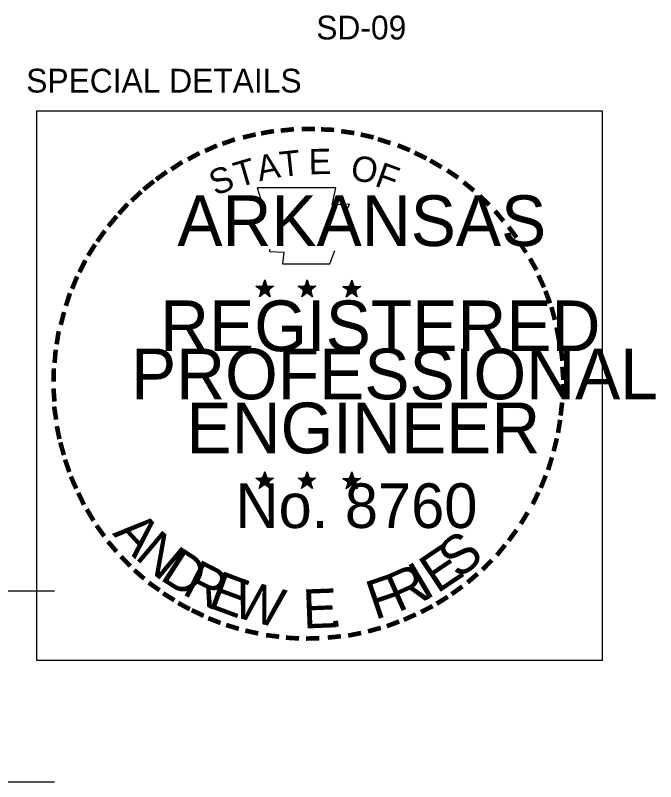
# Model space of a CAD drawing. Extents: x 1227242 to 1227801, y 152460 to 152569.
# Drawn here: x 1227371.723 to 1227374.884, y 152475.874 to 152479.655 of the extents above; entities that cross this region are included whole.
import ezdxf

# ---------------------------------------------------------------- set-up
doc = ezdxf.new("R2010")
doc.units = 0
for name, color, linetype in [('Default', 7, 'Continuous'), ('R_Border', 7, 'Continuous'), ('R_Border PE', 7, 'Continuous'), ('R_Border Prem', 7, 'Continuous')]:
    doc.layers.add(name, color=color, linetype=linetype)

msp = doc.modelspace()

# ---------------------------------------------------------------- linework, layer by layer
at = {"layer": 'Default'}
for p, q in [((1227362.7076, 152476.8155), (1227371.9168, 152476.8155)), ((1227362.7076, 152475.8742), (1227371.9168, 152475.8742))]:
    msp.add_line(p, q, dxfattribs=at)
at = {"layer": 'R_Border PE'}
for p, q in [((1227372.9545, 152478.3508), (1227372.9482, 152478.3196)), ((1227372.9545, 152478.3508), (1227372.9495, 152478.3183)), ((1227372.9545, 152478.3508), (1227372.9532, 152478.3196)), ((1227372.9545, 152478.3046), (1227372.9545, 152478.3508)), ((1227372.9545, 152478.3508), (1227372.9632, 152478.3183)), ((1227372.9545, 152478.3508), (1227372.9607, 152478.3196)), ((1227372.9545, 152478.3508), (1227372.9582, 152478.3196)), ((1227373.1632, 152478.3508), (1227373.157, 152478.3196)), ((1227373.1632, 152478.3508), (1227373.1582, 152478.3183)), ((1227373.1632, 152478.3508), (1227373.1607, 152478.3196)), ((1227373.1632, 152478.3046), (1227373.1632, 152478.3508)), ((1227373.1632, 152478.3508), (1227373.172, 152478.3183)), ((1227373.1632, 152478.3508), (1227373.1695, 152478.3196)), ((1227373.1632, 152478.3508), (1227373.1657, 152478.3196)), ((1227373.3845, 152478.3483), (1227373.377, 152478.3183)), ((1227373.3845, 152478.3483), (1227373.3795, 152478.3171)), ((1227373.3845, 152478.3483), (1227373.382, 152478.3171)), ((1227373.3845, 152478.3033), (1227373.3845, 152478.3483)), ((1227373.3845, 152478.3483), (1227373.3932, 152478.3171)), ((1227373.3845, 152478.3483), (1227373.3907, 152478.3171)), ((1227373.3845, 152478.3483), (1227373.387, 152478.3183)), ((1227372.9107, 152478.3183), (1227372.9545, 152478.3046)), ((1227372.9107, 152478.3183), (1227372.9432, 152478.3158)), ((1227372.9107, 152478.3183), (1227372.9432, 152478.3133)), ((1227372.9107, 152478.3183), (1227372.942, 152478.3108)), ((1227372.9107, 152478.3183), (1227372.942, 152478.3058)), ((1227372.9107, 152478.3183), (1227372.9407, 152478.3033)), ((1227372.9107, 152478.3183), (1227372.9407, 152478.3008)), ((1227372.9982, 152478.3183), (1227372.9545, 152478.3046)), ((1227372.9982, 152478.3183), (1227372.9595, 152478.3158)), ((1227372.9982, 152478.3183), (1227372.962, 152478.3121)), ((1227372.9982, 152478.3183), (1227372.962, 152478.3096)), ((1227372.9982, 152478.3183), (1227372.9707, 152478.3071)), ((1227372.9982, 152478.3183), (1227372.9732, 152478.3058)), ((1227372.9982, 152478.3183), (1227372.9745, 152478.3046)), ((1227373.1195, 152478.3183), (1227373.1632, 152478.3046)), ((1227373.1195, 152478.3183), (1227373.152, 152478.3158)), ((1227373.1195, 152478.3183), (1227373.152, 152478.3133)), ((1227373.1195, 152478.3183), (1227373.1507, 152478.3108)), ((1227373.1195, 152478.3183), (1227373.1495, 152478.3058)), ((1227373.1195, 152478.3183), (1227373.1495, 152478.3033)), ((1227373.1195, 152478.3183), (1227373.1495, 152478.3008)), ((1227373.207, 152478.3183), (1227373.1632, 152478.3046)), ((1227373.207, 152478.3183), (1227373.1682, 152478.3158)), ((1227373.207, 152478.3183), (1227373.1707, 152478.3121)), ((1227373.207, 152478.3183), (1227373.1707, 152478.3096)), ((1227373.207, 152478.3183), (1227373.1795, 152478.3071)), ((1227373.207, 152478.3183), (1227373.182, 152478.3058)), ((1227373.207, 152478.3183), (1227373.1832, 152478.3046)), ((1227373.3407, 152478.3171), (1227373.3845, 152478.3033)), ((1227373.3407, 152478.3171), (1227373.3732, 152478.3133)), ((1227373.3407, 152478.3171), (1227373.372, 152478.3108)), ((1227373.3407, 152478.3171), (1227373.372, 152478.3096)), ((1227373.3407, 152478.3171), (1227373.3707, 152478.3046)), ((1227373.3407, 152478.3171), (1227373.3707, 152478.3021)), ((1227373.3407, 152478.3171), (1227373.3707, 152478.2996)), ((1227373.4282, 152478.3171), (1227373.3845, 152478.3033)), ((1227373.4282, 152478.3171), (1227373.3895, 152478.3146)), ((1227373.4282, 152478.3171), (1227373.392, 152478.3108)), ((1227373.4282, 152478.3171), (1227373.392, 152478.3083)), ((1227373.4282, 152478.3171), (1227373.4007, 152478.3058)), ((1227373.4282, 152478.3171), (1227373.402, 152478.3046)), ((1227373.4282, 152478.3171), (1227373.4045, 152478.3033)), ((1227372.9282, 152478.2671), (1227372.9545, 152478.3046)), ((1227372.9282, 152478.2671), (1227372.942, 152478.3021)), ((1227372.9282, 152478.2671), (1227372.9432, 152478.2983)), ((1227372.9282, 152478.2671), (1227372.9457, 152478.2971)), ((1227372.9282, 152478.2671), (1227372.9545, 152478.2946)), ((1227372.9282, 152478.2671), (1227372.9495, 152478.2933)), ((1227372.9282, 152478.2671), (1227372.9557, 152478.2908)), ((1227372.982, 152478.2671), (1227372.9545, 152478.3046)), ((1227372.982, 152478.2671), (1227372.9545, 152478.2946)), ((1227372.982, 152478.2671), (1227372.9545, 152478.2908)), ((1227372.982, 152478.2671), (1227372.9595, 152478.2933)), ((1227372.982, 152478.2671), (1227372.9632, 152478.2983)), ((1227372.982, 152478.2671), (1227372.9645, 152478.3033)), ((1227372.982, 152478.2671), (1227372.967, 152478.3046)), ((1227373.137, 152478.2671), (1227373.1632, 152478.3046)), ((1227373.137, 152478.2671), (1227373.1507, 152478.3021)), ((1227373.137, 152478.2671), (1227373.152, 152478.2983)), ((1227373.137, 152478.2671), (1227373.1545, 152478.2971)), ((1227373.137, 152478.2671), (1227373.1632, 152478.2946)), ((1227373.137, 152478.2671), (1227373.1582, 152478.2933)), ((1227373.137, 152478.2671), (1227373.1645, 152478.2908)), ((1227373.1907, 152478.2671), (1227373.1632, 152478.3046)), ((1227373.1907, 152478.2671), (1227373.1632, 152478.2946)), ((1227373.1907, 152478.2671), (1227373.1632, 152478.2908)), ((1227373.1907, 152478.2671), (1227373.1682, 152478.2933)), ((1227373.1907, 152478.2671), (1227373.172, 152478.2983)), ((1227373.1907, 152478.2671), (1227373.1732, 152478.3033)), ((1227373.1907, 152478.2671), (1227373.1757, 152478.3046)), ((1227373.357, 152478.2658), (1227373.3845, 152478.3033)), ((1227373.357, 152478.2658), (1227373.372, 152478.3008)), ((1227373.357, 152478.2658), (1227373.3732, 152478.2971)), ((1227373.357, 152478.2658), (1227373.3757, 152478.2958)), ((1227373.357, 152478.2658), (1227373.3845, 152478.2933)), ((1227373.357, 152478.2658), (1227373.3795, 152478.2921)), ((1227373.357, 152478.2658), (1227373.3857, 152478.2896)), ((1227373.4107, 152478.2658), (1227373.3845, 152478.3033)), ((1227373.4107, 152478.2658), (1227373.3845, 152478.2933)), ((1227373.4107, 152478.2658), (1227373.3845, 152478.2896)), ((1227373.4107, 152478.2658), (1227373.3895, 152478.2921)), ((1227373.4107, 152478.2658), (1227373.3932, 152478.2971)), ((1227373.4107, 152478.2658), (1227373.3945, 152478.3021)), ((1227373.4107, 152478.2658), (1227373.397, 152478.3021)), ((1227372.9545, 152477.4033), (1227372.947, 152477.3733)), ((1227372.9545, 152477.4033), (1227372.9495, 152477.3721)), ((1227372.9545, 152477.4033), (1227372.952, 152477.3721)), ((1227372.9545, 152477.3583), (1227372.9545, 152477.4033)), ((1227372.9545, 152477.4033), (1227372.9632, 152477.3721)), ((1227372.9545, 152477.4033), (1227372.9607, 152477.3721)), ((1227372.9545, 152477.4033), (1227372.957, 152477.3721)), ((1227373.1632, 152477.4033), (1227373.1557, 152477.3733)), ((1227373.1632, 152477.4033), (1227373.1582, 152477.3721)), ((1227373.1632, 152477.4033), (1227373.1607, 152477.3721)), ((1227373.1632, 152477.3583), (1227373.1632, 152477.4033)), ((1227373.1632, 152477.4033), (1227373.1707, 152477.3721)), ((1227373.1632, 152477.4033), (1227373.1695, 152477.3721)), ((1227373.1632, 152477.4033), (1227373.1657, 152477.3721)), ((1227373.3845, 152477.4021), (1227373.377, 152477.3708)), ((1227373.3845, 152477.4021), (1227373.3795, 152477.3708)), ((1227373.3845, 152477.4021), (1227373.382, 152477.3708)), ((1227373.3845, 152477.3571), (1227373.3845, 152477.4021)), ((1227373.3845, 152477.4021), (1227373.392, 152477.3708)), ((1227373.3845, 152477.4021), (1227373.3907, 152477.3708)), ((1227373.3845, 152477.4021), (1227373.387, 152477.3708)), ((1227372.9107, 152477.3721), (1227372.9545, 152477.3583)), ((1227372.9107, 152477.3721), (1227372.9432, 152477.3683)), ((1227372.9107, 152477.3721), (1227372.942, 152477.3658)), ((1227372.9107, 152477.3721), (1227372.942, 152477.3646)), ((1227372.9107, 152477.3721), (1227372.9407, 152477.3596)), ((1227372.9107, 152477.3721), (1227372.9407, 152477.3571)), ((1227372.9107, 152477.3721), (1227372.9407, 152477.3546)), ((1227372.9982, 152477.3721), (1227372.9545, 152477.3583)), ((1227372.9982, 152477.3721), (1227372.9595, 152477.3696)), ((1227372.9982, 152477.3721), (1227372.962, 152477.3658)), ((1227372.9982, 152477.3721), (1227372.962, 152477.3633)), ((1227372.9982, 152477.3721), (1227372.9695, 152477.3608)), ((1227372.9982, 152477.3721), (1227372.972, 152477.3596)), ((1227372.9982, 152477.3721), (1227372.9745, 152477.3571)), ((1227373.1195, 152477.3721), (1227373.1632, 152477.3583)), ((1227373.1195, 152477.3721), (1227373.1507, 152477.3683)), ((1227373.1195, 152477.3721), (1227373.1507, 152477.3658)), ((1227373.1195, 152477.3721), (1227373.1507, 152477.3646)), ((1227373.1195, 152477.3721), (1227373.1495, 152477.3596)), ((1227373.1195, 152477.3721), (1227373.1495, 152477.3571)), ((1227373.1195, 152477.3721), (1227373.1495, 152477.3546)), ((1227373.2057, 152477.3721), (1227373.1632, 152477.3583)), ((1227373.2057, 152477.3721), (1227373.1682, 152477.3696)), ((1227373.2057, 152477.3721), (1227373.1707, 152477.3658)), ((1227373.2057, 152477.3721), (1227373.1707, 152477.3633)), ((1227373.2057, 152477.3721), (1227373.1782, 152477.3608)), ((1227373.2057, 152477.3721), (1227373.1807, 152477.3596)), ((1227373.2057, 152477.3721), (1227373.1832, 152477.3571)), ((1227373.3407, 152477.3708), (1227373.3845, 152477.3571)), ((1227373.3407, 152477.3708), (1227373.372, 152477.3671)), ((1227373.3407, 152477.3708), (1227373.372, 152477.3646)), ((1227373.3407, 152477.3708), (1227373.3707, 152477.3621)), ((1227373.3407, 152477.3708), (1227373.3707, 152477.3583)), ((1227373.3407, 152477.3708), (1227373.3695, 152477.3546)), ((1227373.3407, 152477.3708), (1227373.3695, 152477.3521)), ((1227373.427, 152477.3708), (1227373.3845, 152477.3571)), ((1227373.427, 152477.3708), (1227373.3895, 152477.3683)), ((1227373.427, 152477.3708), (1227373.392, 152477.3646)), ((1227373.427, 152477.3708), (1227373.392, 152477.3621)), ((1227373.427, 152477.3708), (1227373.3995, 152477.3596)), ((1227373.427, 152477.3708), (1227373.402, 152477.3571)), ((1227373.427, 152477.3708), (1227373.4032, 152477.3558)), ((1227372.927, 152477.3208), (1227372.9545, 152477.3583)), ((1227372.927, 152477.3208), (1227372.942, 152477.3558)), ((1227372.927, 152477.3208), (1227372.9432, 152477.3508)), ((1227372.927, 152477.3208), (1227372.9457, 152477.3496)), ((1227372.927, 152477.3208), (1227372.9545, 152477.3483)), ((1227372.927, 152477.3208), (1227372.9495, 152477.3471)), ((1227372.927, 152477.3208), (1227372.9545, 152477.3446)), ((1227372.9807, 152477.3208), (1227372.9532, 152477.3446)), ((1227372.9807, 152477.3208), (1227372.9545, 152477.3583)), ((1227372.9807, 152477.3208), (1227372.9545, 152477.3471)), ((1227372.9807, 152477.3208), (1227372.9582, 152477.3471)), ((1227372.9807, 152477.3208), (1227372.9632, 152477.3571)), ((1227372.9807, 152477.3208), (1227372.9632, 152477.3521)), ((1227372.9807, 152477.3208), (1227372.967, 152477.3571)), ((1227373.1357, 152477.3208), (1227373.1632, 152477.3583)), ((1227373.1357, 152477.3208), (1227373.1507, 152477.3558)), ((1227373.1357, 152477.3208), (1227373.152, 152477.3508)), ((1227373.1357, 152477.3208), (1227373.1545, 152477.3496)), ((1227373.1357, 152477.3208), (1227373.1632, 152477.3483)), ((1227373.1357, 152477.3208), (1227373.1582, 152477.3471)), ((1227373.1357, 152477.3208), (1227373.1632, 152477.3446)), ((1227373.1895, 152477.3208), (1227373.162, 152477.3446)), ((1227373.1895, 152477.3208), (1227373.1632, 152477.3583)), ((1227373.1895, 152477.3208), (1227373.1632, 152477.3471)), ((1227373.1895, 152477.3208), (1227373.167, 152477.3471)), ((1227373.1895, 152477.3208), (1227373.172, 152477.3571)), ((1227373.1895, 152477.3208), (1227373.172, 152477.3521)), ((1227373.1895, 152477.3208), (1227373.1757, 152477.3571)), ((1227373.357, 152477.3196), (1227373.3845, 152477.3571)), ((1227373.357, 152477.3196), (1227373.3707, 152477.3546)), ((1227373.357, 152477.3196), (1227373.372, 152477.3496)), ((1227373.357, 152477.3196), (1227373.3757, 152477.3483)), ((1227373.357, 152477.3196), (1227373.3795, 152477.3458)), ((1227373.357, 152477.3196), (1227373.3832, 152477.3458)), ((1227373.357, 152477.3196), (1227373.3845, 152477.3433)), ((1227373.4107, 152477.3196), (1227373.3832, 152477.3458)), ((1227373.4107, 152477.3196), (1227373.3832, 152477.3421)), ((1227373.4107, 152477.3196), (1227373.3845, 152477.3571)), ((1227373.4107, 152477.3196), (1227373.3882, 152477.3458)), ((1227373.4107, 152477.3196), (1227373.392, 152477.3496)), ((1227373.4107, 152477.3196), (1227373.3932, 152477.3558)), ((1227373.4107, 152477.3196), (1227373.3957, 152477.3558))]:
    msp.add_line(p, q, dxfattribs=at)
for points in [[(1227372.917, 152478.8033), (1227372.9495, 152478.6996)], [(1227373.3557, 152478.6883), (1227373.3732, 152478.7233), (1227373.287, 152478.7208), (1227373.3057, 152478.8033), (1227372.917, 152478.8033)], [(1227372.9782, 152478.5008), (1227372.9782, 152478.4896), (1227373.0482, 152478.4871), (1227373.042, 152478.4283), (1227373.2757, 152478.4283), (1227373.3007, 152478.4946)], [(1227372.9545, 152478.3508), (1227372.982, 152478.2671), (1227372.9107, 152478.3183), (1227372.9982, 152478.3183), (1227372.9282, 152478.2671), (1227372.9545, 152478.3508)], [(1227373.1632, 152478.3508), (1227373.1907, 152478.2671), (1227373.1195, 152478.3183), (1227373.207, 152478.3183), (1227373.137, 152478.2671), (1227373.1632, 152478.3508)], [(1227373.3845, 152478.3483), (1227373.4107, 152478.2658), (1227373.3407, 152478.3171), (1227373.4282, 152478.3171), (1227373.357, 152478.2658), (1227373.3845, 152478.3483)], [(1227372.9545, 152477.4033), (1227372.9807, 152477.3208), (1227372.9107, 152477.3721), (1227372.9982, 152477.3721), (1227372.927, 152477.3208), (1227372.9545, 152477.4033)], [(1227373.1632, 152477.4033), (1227373.1895, 152477.3208), (1227373.1195, 152477.3721), (1227373.2057, 152477.3721), (1227373.1357, 152477.3208), (1227373.1632, 152477.4033)], [(1227373.3845, 152477.4021), (1227373.4107, 152477.3196), (1227373.3407, 152477.3708), (1227373.427, 152477.3708), (1227373.357, 152477.3196), (1227373.3845, 152477.4021)]]:
    msp.add_lwpolyline(points, dxfattribs=at)
for centre, radius in [((1227372.9549, 152478.3045), 0.0215), ((1227372.9549, 152478.3045), 0.0195), ((1227372.9549, 152478.3045), 0.0181), ((1227372.9549, 152478.3045), 0.0166), ((1227372.9549, 152478.3045), 0.0145), ((1227372.9549, 152478.3045), 0.0134), ((1227372.9549, 152478.3045), 0.0124), ((1227372.9549, 152478.3045), 0.0107), ((1227372.9549, 152478.3045), 0.00934), ((1227372.9549, 152478.3045), 0.00777), ((1227372.9549, 152478.3045), 0.00619), ((1227372.9549, 152478.3045), 0.00462), ((1227372.9549, 152478.3045), 0.00371), ((1227372.9549, 152478.3045), 0.0018), ((1227373.1635, 152478.3045), 0.0215), ((1227373.1635, 152478.3045), 0.0195), ((1227373.1635, 152478.3045), 0.0181), ((1227373.1635, 152478.3045), 0.0166), ((1227373.1635, 152478.3045), 0.0145), ((1227373.1635, 152478.3045), 0.0134), ((1227373.1635, 152478.3045), 0.0124), ((1227373.1635, 152478.3045), 0.0107), ((1227373.1635, 152478.3045), 0.00934), ((1227373.1635, 152478.3045), 0.00777), ((1227373.1635, 152478.3045), 0.00619), ((1227373.1635, 152478.3045), 0.00462), ((1227373.1635, 152478.3045), 0.00371), ((1227373.1635, 152478.3045), 0.0018), ((1227373.3844, 152478.303), 0.0215), ((1227373.3844, 152478.303), 0.0195), ((1227373.3844, 152478.303), 0.0181), ((1227373.3844, 152478.303), 0.0166), ((1227373.3844, 152478.303), 0.0145), ((1227373.3844, 152478.303), 0.0134), ((1227373.3844, 152478.303), 0.0124), ((1227373.3844, 152478.303), 0.0107), ((1227373.3844, 152478.303), 0.00934), ((1227373.3844, 152478.303), 0.00777), ((1227373.3844, 152478.303), 0.00619), ((1227373.3844, 152478.303), 0.00462), ((1227373.3844, 152478.303), 0.00371), ((1227373.3844, 152478.303), 0.0018), ((1227372.9543, 152477.3578), 0.0215), ((1227372.9543, 152477.3578), 0.0195), ((1227372.9543, 152477.3578), 0.0181), ((1227372.9543, 152477.3578), 0.0166), ((1227372.9543, 152477.3578), 0.0145), ((1227372.9543, 152477.3578), 0.0134), ((1227372.9543, 152477.3578), 0.0124), ((1227372.9543, 152477.3578), 0.0107), ((1227372.9543, 152477.3578), 0.00934), ((1227372.9543, 152477.3578), 0.00777), ((1227372.9543, 152477.3578), 0.00619), ((1227372.9543, 152477.3578), 0.00462), ((1227372.9543, 152477.3578), 0.00371), ((1227372.9543, 152477.3578), 0.0018), ((1227373.163, 152477.3578), 0.0215), ((1227373.163, 152477.3578), 0.0195), ((1227373.163, 152477.3578), 0.0181), ((1227373.163, 152477.3578), 0.0166), ((1227373.163, 152477.3578), 0.0145), ((1227373.163, 152477.3578), 0.0134), ((1227373.163, 152477.3578), 0.0124), ((1227373.163, 152477.3578), 0.0107), ((1227373.163, 152477.3578), 0.00934), ((1227373.163, 152477.3578), 0.00777), ((1227373.163, 152477.3578), 0.00619), ((1227373.163, 152477.3578), 0.00462), ((1227373.163, 152477.3578), 0.00371), ((1227373.163, 152477.3578), 0.0018), ((1227373.3839, 152477.3564), 0.0215), ((1227373.3839, 152477.3564), 0.0195), ((1227373.3839, 152477.3564), 0.0181), ((1227373.3839, 152477.3564), 0.0166), ((1227373.3839, 152477.3564), 0.0145), ((1227373.3839, 152477.3564), 0.0134), ((1227373.3839, 152477.3564), 0.0124), ((1227373.3839, 152477.3564), 0.0107), ((1227373.3839, 152477.3564), 0.00934), ((1227373.3839, 152477.3564), 0.00777), ((1227373.3839, 152477.3564), 0.00619), ((1227373.3839, 152477.3564), 0.00462), ((1227373.3839, 152477.3564), 0.00371), ((1227373.3839, 152477.3564), 0.0018)]:
    msp.add_circle(centre, radius, dxfattribs=at)
at = {"layer": 'R_Border Prem'}
msp.add_lwpolyline([(1227371.8301, 152479.1842), (1227374.6201, 152479.1842), (1227374.6201, 152476.4718), (1227371.8301, 152476.4718)], close=True, dxfattribs=at)

# ---------------------------------------------------------------- texts
at = {"layer": 'R_Border'}
for s, height, p in [('SD-09', 0.11723, (1227373.2089, 152479.5362)), ('SPECIAL DETAILS', 0.11724, (1227371.7773, 152479.2742))]:
    msp.add_text(s, height=height, dxfattribs=at).set_placement(p)
at = {"layer": 'R_Border PE'}
for s, height, rotation, p in [('-', 0.2, 5.8968, (1227373.0295, 152479.0083)), ('-', 0.2, 0.1862, (1227373.1257, 152479.0171)), ('-', 0.2, 357.743, (1227373.217, 152479.0158)), ('-', 0.2, 13.6302, (1227372.8532, 152478.9746)), ('-', 0.2, 10.2193, (1227372.9382, 152478.9946)), ('-', 0.2, 352.1617, (1227373.3095, 152479.0083)), ('-', 0.2, 347.2049, (1227373.3995, 152478.9946)), ('-', 0.2, 24.3072, (1227372.6807, 152478.9108)), ('-', 0.2, 19.1761, (1227372.7595, 152478.9446)), ('-', 0.2, 342.3362, (1227373.4782, 152478.9746)), ('-', 0.2, 337.8551, (1227373.5707, 152478.9471)), ('-', 0.2, 28.7918, (1227372.602, 152478.8708)), ('T', 0.125, 6.0228, (1227373.0345, 152478.8571)), ('E', 0.125, 0.8323, (1227373.172, 152478.8708)), ('-', 0.2, 334.1211, (1227373.6495, 152478.9133)), ('T', 0.125, 16.4036, (1227372.8245, 152478.8046)), ('A', 0.125, 11.2132, (1227372.9282, 152478.8358)), ('O', 0.125, 350.4515, (1227373.3732, 152478.8446)), ('-', 0.2, 329.6409, (1227373.722, 152478.8783)), ('-', 0.2, 34.0636, (1227372.527, 152478.8246)), ('F', 0.125, 340.0707, (1227373.492, 152478.8158)), ('-', 0.2, 36.2317, (1227372.4545, 152478.7758)), ('S', 0.125, 21.594, (1227372.7107, 152478.7633)), ('-', 0.2, 325.8627, (1227373.802, 152478.8333)), ('-', 0.2, 38.9507, (1227372.3957, 152478.7283)), ('-', 0.2, 320.5297, (1227373.8782, 152478.7796)), ('-', 0.2, 42.9622, (1227372.3407, 152478.6758)), ('-', 0.2, 315.5786, (1227373.9532, 152478.7183)), ('-', 0.2, 48.423, (1227372.2845, 152478.6158)), ('-', 0.2, 309.8797, (1227374.0245, 152478.6496)), ('-', 0.2, 50.6142, (1227372.2345, 152478.5558)), ('-', 0.2, 306.6522, (1227374.0895, 152478.5746)), ('-', 0.2, 54.2325, (1227372.1832, 152478.4846)), ('-', 0.175, 303.6753, (1227374.1507, 152478.5033)), ('-', 0.2, 58.0706, (1227372.142, 152478.4183)), ('-', 0.2, 299.6684, (1227374.1907, 152478.4271)), ('-', 0.2, 62.8713, (1227372.1032, 152478.3421)), ('-', 0.2, 67.7743, (1227372.0707, 152478.2658)), ('-', 0.2, 294.6628, (1227374.2307, 152478.3508)), ('-', 0.2, 72.3945, (1227372.0432, 152478.1871)), ('-', 0.2, 290.5728, (1227374.2632, 152478.2796)), ('-', 0.2, 75.461, (1227372.0195, 152478.0971)), ('-', 0.2, 285.1233, (1227374.292, 152478.2071)), ('-', 0.2, 280.5493, (1227374.317, 152478.1133)), ('-', 0.2, 81.2013, (1227372.002, 152478.0083)), ('-', 0.2, 85.1863, (1227371.9932, 152477.9221)), ('-', 0.2, 276.5962, (1227374.3382, 152478.0183)), ('-', 0.2, 89.0622, (1227371.9895, 152477.8346)), ('-', 0.2, 274.3301, (1227374.3457, 152477.9271)), ('-', 0.2, 94.1959, (1227371.9945, 152477.7433)), ('-', 0.2, 269.9407, (1227374.3495, 152477.8483)), ('-', 0.2, 263.5172, (1227374.347, 152477.7658)), ('-', 0.2, 98.9479, (1227372.0032, 152477.6608)), ('-', 0.2, 101.7149, (1227372.0195, 152477.5683)), ('-', 0.2, 260.9953, (1227374.3382, 152477.6833)), ('-', 0.2, 105.4578, (1227372.0407, 152477.4946)), ('-', 0.2, 255.7626, (1227374.3245, 152477.5983)), ('-', 0.2, 252.8681, (1227374.302, 152477.5083)), ('-', 0.2, 109.0874, (1227372.067, 152477.4158)), ('-', 0.2, 114.0643, (1227372.0995, 152477.3408)), ('-', 0.2, 247.8887, (1227374.2745, 152477.4246)), ('-', 0.2, 115.7289, (1227372.137, 152477.2633)), ('-', 0.2, 244.6197, (1227374.2407, 152477.3458)), ('-', 0.2, 120.4471, (1227372.182, 152477.1908)), ('A', 0.1925, 312.4727, (1227372.1995, 152477.0969)), ('-', 0.2, 239.0712, (1227374.192, 152477.2521)), ('-', 0.2, 125.8934, (1227372.232, 152477.1208)), ('N', 0.1925, 319.8362, (1227372.3081, 152476.9783)), ('S', 0.1925, 39.723, (1227373.9128, 152476.869)), ('-', 0.2, 233.8452, (1227374.142, 152477.1708)), ('-', 0.2, 130.7181, (1227372.2895, 152477.0508)), ('D', 0.1925, 327.1996, (1227372.4311, 152476.8746)), ('E', 0.1925, 33.8878, (1227373.806, 152476.7993)), ('-', 0.2, 231.2538, (1227374.0882, 152477.0996)), ('-', 0.2, 134.2238, (1227372.3545, 152476.9833)), ('R', 0.1925, 333.1738, (1227372.54, 152476.8025)), ('I', 0.1925, 30.5534, (1227373.742, 152476.7645)), ('-', 0.2, 225.7653, (1227374.0282, 152477.0296)), ('-', 0.2, 138.9338, (1227372.4195, 152476.9258)), ('E', 0.1925, 339.7037, (1227372.6668, 152476.7372)), ('R', 0.1925, 24.0235, (1227373.6113, 152476.7073)), ('-', 0.2, 221.0851, (1227373.9632, 152476.9658)), ('W', 0.1925, 345.5389, (1227372.7858, 152476.6914)), ('F', 0.1925, 18.6051, (1227373.4984, 152476.6714)), ('-', 0.2, 144.6463, (1227372.4895, 152476.8746)), ('-', 0.2, 215.7363, (1227373.8945, 152476.9071)), ('-', 0.2, 148.0898, (1227372.5595, 152476.8283)), ('E', 0.1925, 2.2804, (1227373.1452, 152476.6295)), ('-', 0.2, 212.2491, (1227373.827, 152476.8583)), ('-', 0.2, 151.5704, (1227372.632, 152476.7871)), ('-', 0.2, 154.6002, (1227372.697, 152476.7571)), ('-', 0.2, 207.3568, (1227373.7582, 152476.8146)), ('-', 0.2, 158.5612, (1227372.7757, 152476.7246)), ('-', 0.2, 204.2516, (1227373.6795, 152476.7746)), ('-', 0.2, 162.7983, (1227372.8607, 152476.6983)), ('.', 0.1925, 8.1156, (1227373.2727, 152476.6329)), ('-', 0.2, 195.4743, (1227373.5182, 152476.7108)), ('-', 0.2, 200.7184, (1227373.602, 152476.7408)), ('-', 0.2, 167.5555, (1227372.9507, 152476.6783)), ('-', 0.2, 173.1155, (1227373.047, 152476.6646)), ('-', 0.2, 191.2858, (1227373.427, 152476.6858)), ('-', 0.2, 176.5183, (1227373.1407, 152476.6571)), ('-', 0.2, 181.5918, (1227373.2332, 152476.6596)), ('-', 0.2, 185.8167, (1227373.3345, 152476.6696))]:
    msp.add_text(s, height=height, rotation=rotation, dxfattribs=at).set_placement(p)
for s, height, p in [('ARKANSAS', 0.25, (1227372.5232, 152478.5171)), ('REGISTERED', 0.25, (1227372.4382, 152477.9983)), ('PROFESSIONAL', 0.249997, (1227372.2945, 152477.7608)), ('ENGINEER', 0.25, (1227372.5682, 152477.4946)), ('No. 8760', 0.22, (1227372.8104, 152477.1258))]:
    msp.add_text(s, height=height, dxfattribs=at).set_placement(p)

doc.saveas('drawing.dxf')
